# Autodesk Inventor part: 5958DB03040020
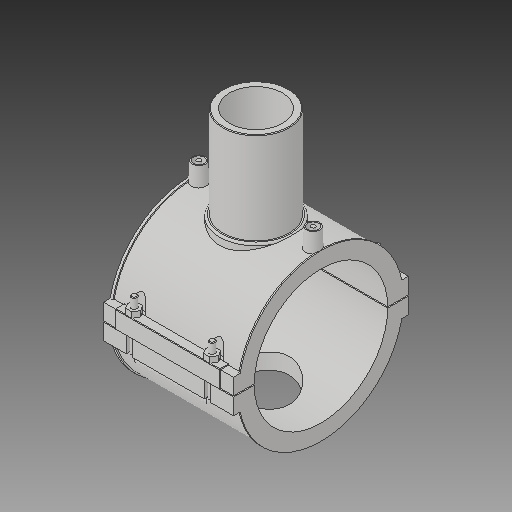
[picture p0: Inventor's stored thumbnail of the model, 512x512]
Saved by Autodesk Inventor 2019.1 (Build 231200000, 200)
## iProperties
Created: 2017-07
Part Number: 5958DB03040020
Material: Generic
Description: PLASSON BRANCH SADDLE 4''DIPS x 2''IPS
Document SubType Name: Modeling
Designer: KIM
Mass: 764.267 g
Surface Area: 1930.38 cm^2
Volume: 764.267 cm^3
Density: 1 g/cm^3
Appearance: Default
Author: KIM
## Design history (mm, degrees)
derived "5958D (1).ipt"
feature "Solid6::5958D (1).ipt"
feature "Solid7::5958D (1).ipt"
feature "Solid8::5958D (1).ipt"
tag "TaggingFeature1"
body "Solid1"
body "Solid2"
body "Solid3"
other parameters: "d_" = 121.3, "d1" = 60.1, "B_" = 159.004, "H_" = 97.028, "H1" = 83.82, "L" = 118.11, "t" = 6, "d244" = 121.3, "d245" = 13.208, "d246" = 30.325, "d247" = 30.325, "d248" = 159.004, "d249" = 79.502, "d250" = 1, "d252" = 60.65, "d253" = 60.65, "d254" = 13.208, "d255" = 13.208, "d256" = 159.004, "d257" = 15.1625, "d258" = 79.502, "d259" = 0.5, "d260" = 118.11, "d261" = 0, "d262" = 70.866, "d263" = 6, "d271" = 0, "d272" = 3, "d274" = 3, "d277" = 3, "d278" = 3, "d279" = 5.4, "d280" = 0, "d281" = 0, "d283" = 30.325, "d284" = 0.6, "d287" = 74.38632, "d288" = 66.11, "d290" = 0, "d291" = 157.678, "d292" = 60.1, "d294" = 0, "d295" = 3, "d296" = 15, "d297" = 15, "d298" = 25.4, "d299" = 0, "d300" = 1, "d302" = 94.488, "d303" = 0, "d306" = 5, "d307" = 0, "d308" = 1, "d309" = 90.65, "d310" = 12, "d311" = 12, "d315" = 3 deg, "d316" = 4, "d318" = 4, "d320" = 14, "d321" = 0, "d322" = 0.5, "d323" = 1.213, "d324" = 1.213, "d325" = 2.3622, "d326" = 0, "d327" = 1.1811, "d328" = 1.1811, "d329" = 1.1811, "d330" = 0, "d331" = 1.803, "d332" = 48.08, "d334" = 0, "d336" = 0, "d337" = 0.601, "d340" = 7.0866, "d341" = 7.0866
